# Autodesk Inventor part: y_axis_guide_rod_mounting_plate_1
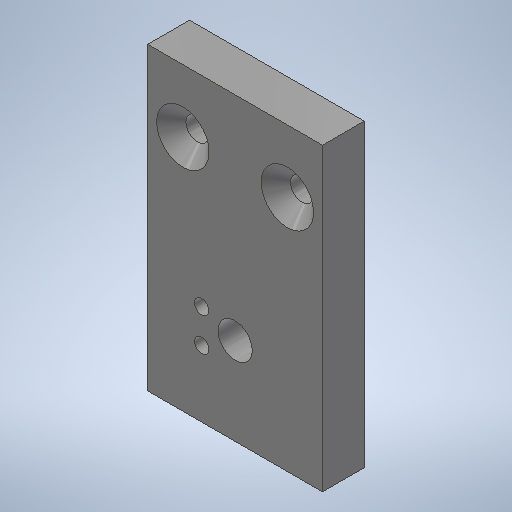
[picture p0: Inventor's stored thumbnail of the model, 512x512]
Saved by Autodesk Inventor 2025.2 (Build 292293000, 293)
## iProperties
Created: 2025-04
Part Number: y_axis_guide_rod_mounting_plate_1
Material: 1.0037 S235JR
Document SubType Name: Modeling
Designer: BennF
Density: 7.85 g/cm^3
Appearance: Stahl
Author: BennF
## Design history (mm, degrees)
sketch "Sketch2"
  geometry: L1 (20.9, 35.9)-(-20.9, 35.9); L2 (-20.9, 35.9)-(-20.9, -35.9); L3 (-20.9, -35.9)-(20.9, -35.9); L4 (20.9, -35.9)-(20.9, 35.9); 3 further points
  constraints: 8 end point, 2 midpoint, 2 parallel, 1 horizontal, 1 horizontal alignment, 1 perpendicular, 1 vertical alignment
  dimensions: "d0" = 41.8 distance of L1.start L1.end; "d1" = 71.8 distance of L3.end L1.start (computed from d0)
extrude "Extrusion1" new body sketch "Sketch2" distance "d2" = 10; taper "d3" = 0 deg
sketch "Sketch3"
  geometry: L1 (-12.5, 20.9)-(12.5, 20.9); L2 (-20.9, 35.9)-(20.9, 35.9) reference; 2 further points
  constraints: 2 end point, 1 horizontal, 1 horizontal alignment, 1 midpoint, 1 vertical alignment
  dimensions: "d11" = 25 distance of L1.start L1.end; "d12" = 15 distance between parallel lines of L2 L1
hole "Hole1" sketch "Sketch3" at (-12.5, 20.9), (12.5, 20.9) diameter "d4" = 5.5; stored, may be unused: countersink angle "d8" = 90 deg, drill point angle "d10" = 118 deg; dims "d5" = 6, "d6" = 12.5, "d7" = 2, "d9" = 8
sketch "Sketch4"
  geometry: L1 (20.9, -35.9)-(-20.9, -35.9) reference; 2 further points
  constraints: 1 vertical alignment
  dimensions: "d20" = -20.9 distance from line of L1 point (0, -15)
hole "Hole2" sketch "Sketch4" at (0, -15) diameter "d13" = 8.15; stored, may be unused: countersink angle "d17" = 90 deg, drill point angle "d19" = 118 deg; dims "d14" = 6, "d15" = 12.5, "d16" = 2, "d18" = 8
sketch "Sketch5"
  geometry: L1 (-8, 12)-(-8, 20); C1 r 4.075 at (0, 15) reference; 1 further point
  constraints: 2 end point, 1 vertical, 1 vertical alignment
  dimensions: "d28" = 8 distance of L1.start L1.end; "d29" = 8 distance from line of L1 C1.centre; "d30" = 3 vertical distance of L1.start C1.centre
hole "Hole3" sketch "Sketch5" at (-8, 12), (-8, 20) diameter "d21" = 3.4; stored, may be unused: countersink angle "d25" = 90 deg, drill point angle "d27" = 118 deg; dims "d22" = 6, "d23" = 7.5, "d24" = 2, "d26" = 8
body "Solid1"
